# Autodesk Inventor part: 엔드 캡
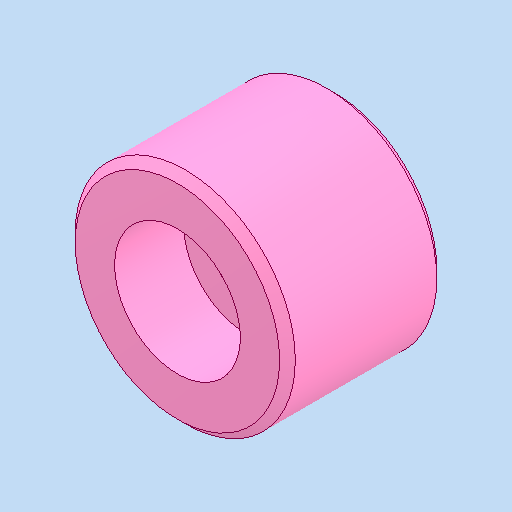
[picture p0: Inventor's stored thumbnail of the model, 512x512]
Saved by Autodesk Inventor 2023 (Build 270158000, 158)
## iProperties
Created: 2026-04
Part Number: 엔드 캡
Material: 강철, 연강
Document SubType Name: Modeling
Designer: home
Density: 7.85 g/cm^3
Appearance: 기본값
Author: jhkim
Sending System: Autodesk Inventor 2027
Preprocessor: ST-DEVELOPER v20.1
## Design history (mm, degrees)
feature "솔리드1"
node "솔리드2"
